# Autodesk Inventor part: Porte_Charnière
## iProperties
Created: 2009-01
Part Number: Porte_Charnière
Document SubType Name: Modeling
Designer: claivier
Author: claivier
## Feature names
1. Extrusion1
2. Extrusion2
3. Réseau rectangulaire1 [Rectangular Pattern]
4. Perçage1 [Hole]
5. Extrusion3
